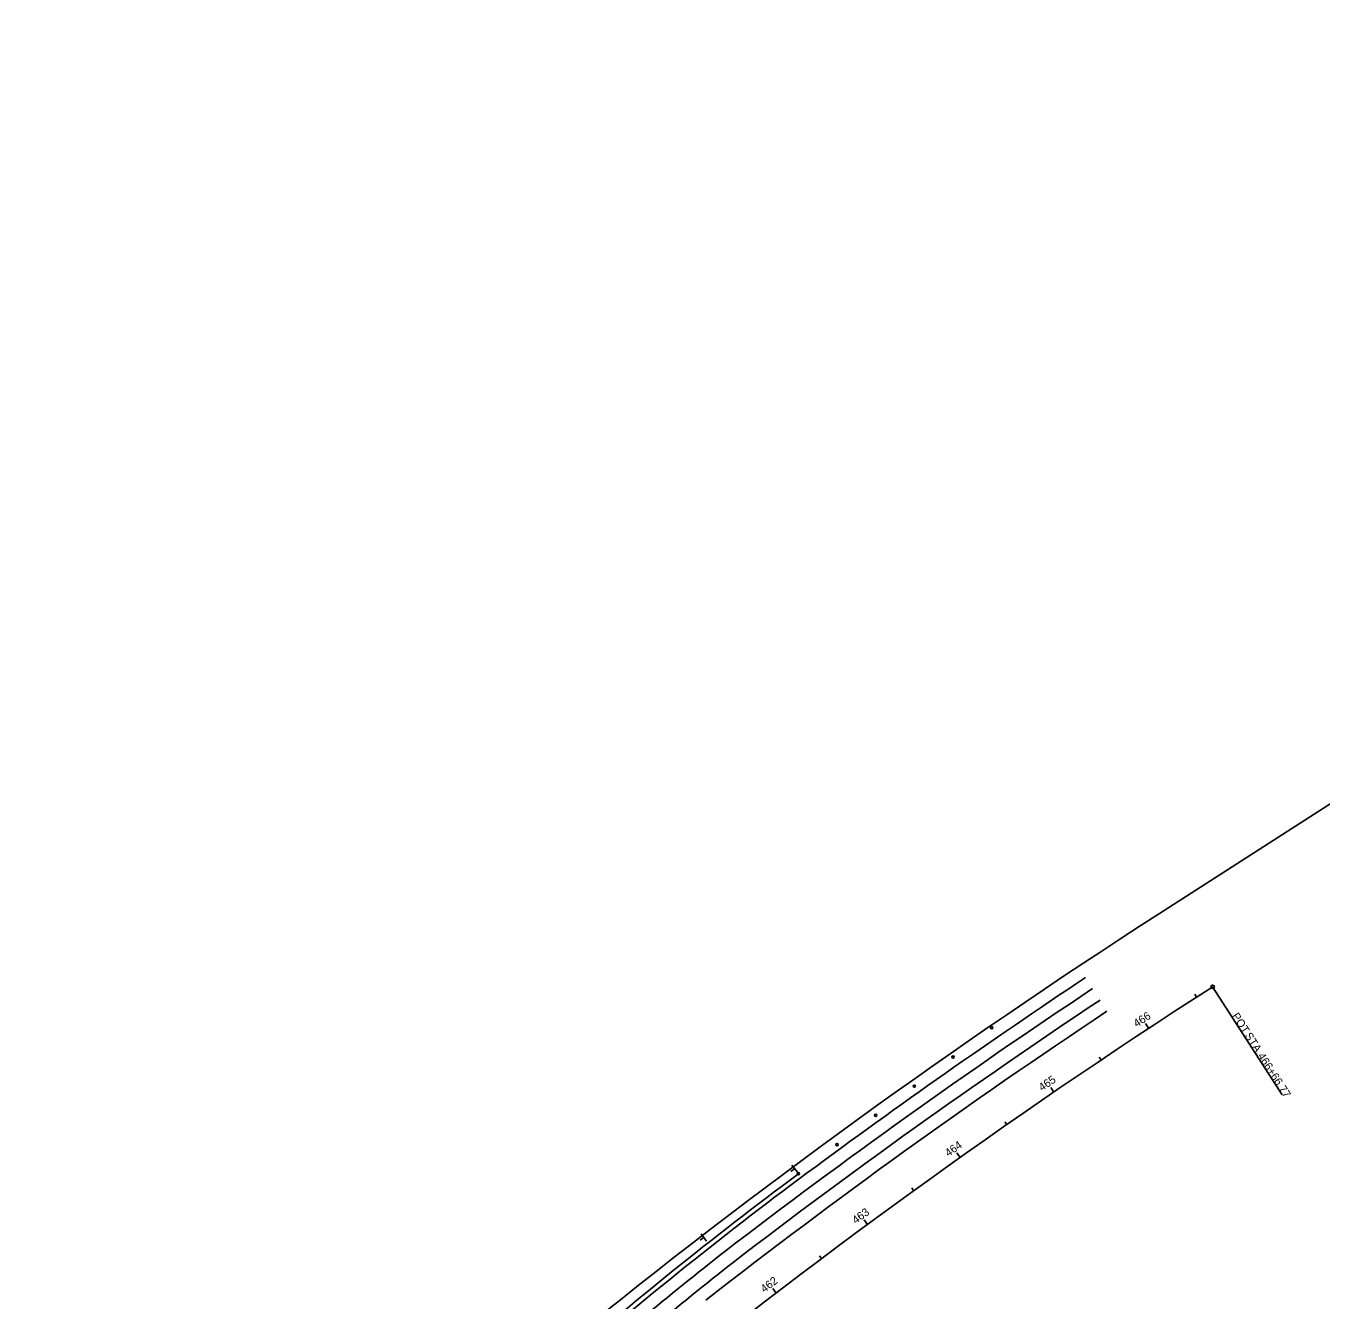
# Model space of a CAD drawing. Extents: x 142554 to 147512, y 370190 to 373751.
# Drawn here: x 145312 to 146445, y 372636 to 373751 of the extents above; entities that cross this region are included whole.
import ezdxf

# ---------------------------------------------------------------- set-up
doc = ezdxf.new("R2010")
doc.units = 0
for name, color, linetype in [('DR_P_Cells', 7, 'Continuous'), ('DR_X_GenericNode', 7, 'Continuous'), ('FeatureService_Stream Network', 7, 'Continuous'), ('PM_X_Channelizing_Line', 7, 'Continuous'), ('PM_X_Edge_Line', 7, 'Continuous'), ('RD_X_GR_Cable_Bar', 7, 'Continuous'), ('RD_X_GR_Lt', 7, 'Continuous'), ('SC_Scratch20', 7, 'Continuous')]:
    doc.layers.add(name, color=color, linetype=linetype)

msp = doc.modelspace()

# ---------------------------------------------------------------- linework, layer by layer
at = {"layer": 'DR_P_Cells'}
for centre, radius, start, end in [((149413.6, 368136.5), 5728, 123.5811, 127.5388), ((149413.6, 368136.5), 5716, 123.5822, 127.5382), ((148078, 369935.4), 3488, 128.1463, 131.2155), ((148078, 369935.4), 3476, 128.1473, 131.2155)]:
    msp.add_arc(centre, radius, start, end, dxfattribs=at)
at = {"layer": 'DR_X_GenericNode'}
for centre, radius, start, end in [((149483, 368037.7), 5860.2, 123.61023, 126.51543), ((149412.8, 368137.2), 5703.5, 123.5834, 127.9279), ((148078.6, 369934.6), 3500, 126.5154, 131.2155)]:
    msp.add_arc(centre, radius, start, end, dxfattribs=at)
at = {"layer": 'FeatureService_Stream Network'}
for centre in [(146157.2, 372874.3), (146123.3, 372848.7), (146089.5, 372823.2), (146055.6, 372797.7), (146021.8, 372772.1), (145988, 372746.6)]:
    msp.add_circle(centre, 1, dxfattribs=at)
msp.add_arc((148077.2, 369936), 3502, 126.6251, 131.2155, dxfattribs=at)
at = {"layer": 'PM_X_Channelizing_Line'}
msp.add_line((146350.4, 372910.2), (146411.3, 372815.6), dxfattribs=at)
msp.add_circle((146350.4, 372910.2), 1.5, dxfattribs=at)
at = {"layer": 'PM_X_Edge_Line'}
msp.add_arc((149448.4, 368090.4), 5729.6, 122.7308, 135.5169, dxfattribs=at)
msp.add_arc((149448.4, 368090.4), 5729.6, 122.7308, 135.5169, dxfattribs=at)
at = {"layer": 'RD_X_GR_Cable_Bar'}
for p, q in [((146336.3, 372901.1), (146334.7, 372903.6)), ((146294.5, 372873.8), (146291.7, 372877.9)), ((146252.9, 372846.1), (146251.2, 372848.6)), ((146211.5, 372818), (146208.7, 372822.1)), ((146170.3, 372789.6), (146168.6, 372792)), ((146129.5, 372760.8), (146126.6, 372764.9)), ((146088.8, 372731.6), (146087.1, 372734.1)), ((146048.5, 372702.2), (146045.5, 372706.2)), ((146008.3, 372672.3), (146006.5, 372674.7)), ((145968.5, 372642.1), (145965.5, 372646.1))]:
    msp.add_line(p, q, dxfattribs=at)
at = {"layer": 'RD_X_GR_Lt'}
for p, q in [((145984.7, 372751), (145981.5, 372748.6)), ((145982.3, 372754.2), (145987.1, 372747.8)), ((145984.7, 372751), (145984.7, 372751)), ((145905.3, 372690.9), (145902.1, 372688.5)), ((145902.9, 372694.1), (145907.7, 372687.7)), ((145905.3, 372690.9), (145905.3, 372690.9))]:
    msp.add_line(p, q, dxfattribs=at)
at = {"layer": 'SC_Scratch20'}
msp.add_line((146303.8, 372974.2), (147512.4, 373751), dxfattribs=at)
msp.add_arc((149412.8, 368137.2), 5750, 122.73083, 135.49226, dxfattribs=at)

# ---------------------------------------------------------------- texts
at = {"layer": 'PM_X_Channelizing_Line'}
for s, p in [('POT', (146366.9, 372884.7)), (' STA. ', (146376.7, 372869.6)), ('466+66.77', (146389.4, 372849.7))]:
    msp.add_text(s, height=7, rotation=302.7308, dxfattribs=at).set_placement(p)
at = {"layer": 'RD_X_GR_Cable_Bar'}
for s, rotation, p in [('466', 33.3985, (146284, 372874.4)), ('465', 34.3985, (146201.1, 372818.5)), ('464', 35.3985, (146119.2, 372761.1)), ('463', 36.3985, (146038.2, 372702.3)), ('462', 37.3985, (145958.2, 372642.1))]:
    msp.add_text(s, height=7, rotation=rotation, dxfattribs=at).set_placement(p)

doc.saveas('drawing.dxf')
